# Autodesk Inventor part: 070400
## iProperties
Shininess: 69.0
Length Units: 11269
Angle Units: 11279
Time Units: 11290
Mass Units: 11284
Length Display Precision: 3
Angle Display Precision: 2
Compacted: True
Company: Pneumax S.p.A.
Part Number: 070400
Material: Default
Description: PROLUNGA Ø4
Document SubType Name: Modellazione
Catalog Web Link: www.pneumaxspa.com
Density: 1.59
Volumn: 0.8648857994912436
Area: 17.092995283760587
PropertySet Name: Model Information
Control State: 0
Master: False
Checked Out: False
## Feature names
1. Chamfer10
